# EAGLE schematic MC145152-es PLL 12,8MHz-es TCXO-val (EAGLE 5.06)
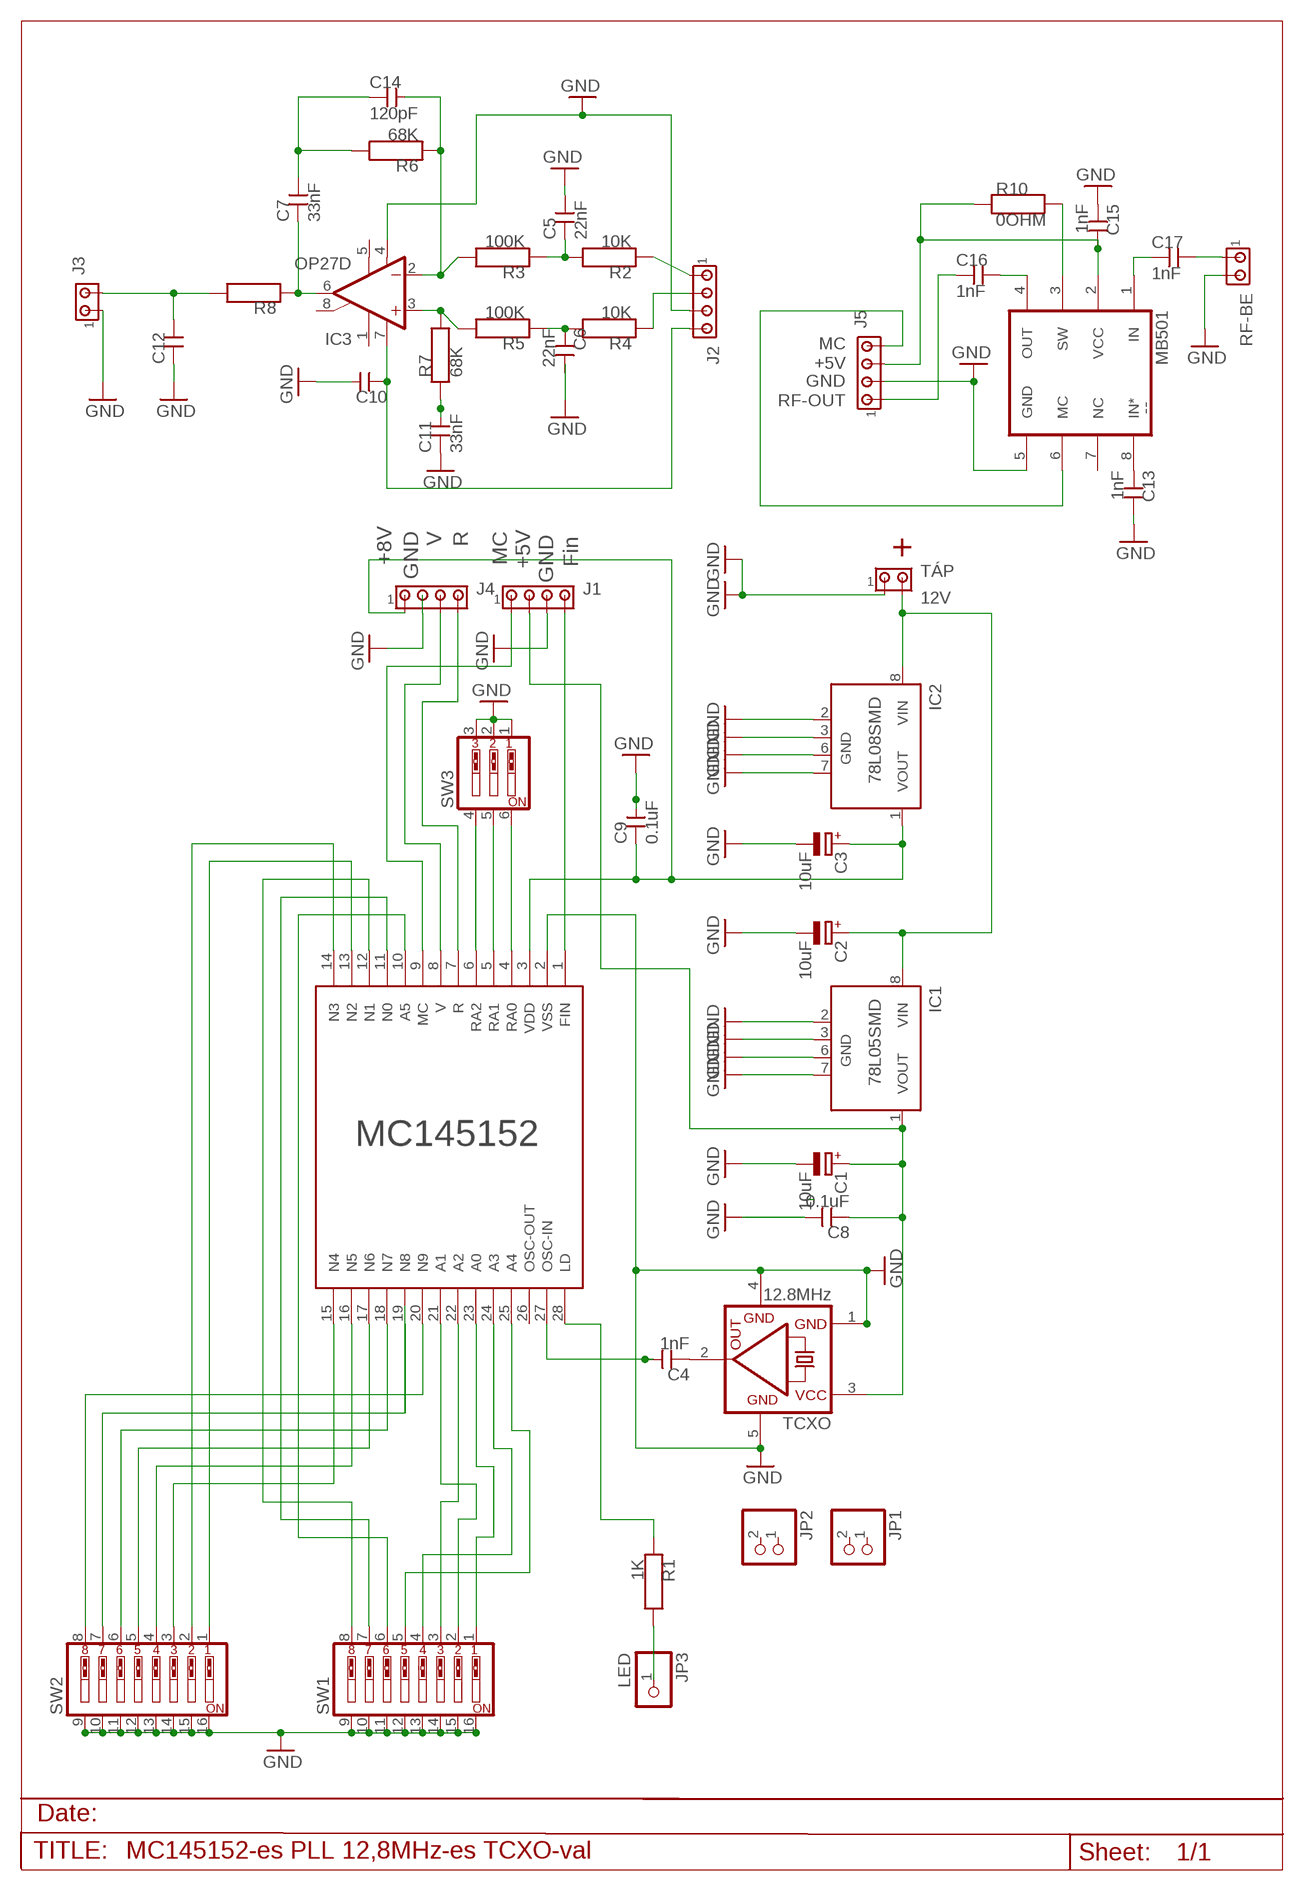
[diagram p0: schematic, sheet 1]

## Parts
C1  10uF  CPOL-EUE2,5-6E  [E2,5-6E]
C2  10uF  CPOL-EUE2,5-6E  [E2,5-6E]
C3  10uF  CPOL-EUE2,5-6E  [E2,5-6E]
C4  1nF  CAP-0805  [0805]
C5  22nF  CAP-0805  [0805]
C6  22nF  CAP-0805  [0805]
C7  33nF  CAP-0805  [0805]
C8  0.1uF  CAP-0805  [0805]
C9  0.1uF  CAP-0805  [0805]
C10  CAP-0805  [0805]
C11  33nF  CAP-0805  [0805]
C12  CAP-0805  [0805]
C13  1nF  CAP-0805  [0805]
C14  120pF  CAP-0805  [0805]
C15  1nF  CAP-0805  [0805]
C16  1nF  CAP-0805  [0805]
C17  1nF  CAP-0805  [0805]
IC1  78L05SMD  [SO08]
IC2  78L08SMD  [SO08]
IC3  OP27D  [SO08]
J1  MTA04-100  [10X04MTA]
J2  MTA04-100  [10X04MTA]
J3  MTA02-100  [10X02MTA]
J4  MTA04-100  [10X04MTA]
J5  MTA04-100  [10X04MTA]
JP1  PINHD-1X2_2.54  [1X02]
JP2  PINHD-1X2_2.54  [1X02]
JP3  LED  PINHD-1X1_2.54  [1X01]
MB501  MB501  [SO08]
MC145152  MC145152  [DIL28]
R1  1K  RES-0805  [0805]
R2  10K  RES-0805  [0805]
R3  100K  RES-0805  [0805]
R4  10K  RES-0805  [0805]
R5  100K  RES-0805  [0805]
R6  68K  RES-0805  [0805]
R7  68K  RES-0805  [0805]
R8  RES-0805  [0805]
R10  0OHM  RES-0805  [0805]
RF-BE  MTA02-100  [10X02MTA]
SW1  SW_DIP-8  [DIPSWITCH-08]
SW2  SW_DIP-8  [DIPSWITCH-08]
SW3  SW_DIP-3  [EDG-03]
TCXO  12.8MHz  TCXO  [TCXO]
TÁP  12V  MTA02-100  [10X02MTA]
U$1  FRAMES-A4  [FRAMES-A4]

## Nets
GND: C1.- C2.- C3.- C5.P$2 C6.P$2 C8.P$2 C9.P$2 C10.P$2 C11.P$1 C12.P$1 C13.P$2 C15.P$1 IC1.2(GND) IC1.3(GND) IC1.6(GND) IC1.7(GND) IC2.2(GND) IC2.3(GND) IC2.6(GND) IC2.7(GND) IC3.4(V-) J1.3 J2.3 J3.1 J4.2 J5.2 MB501.5(GND) MC145152.2(VSS) RF-BE.2 SW1.9 SW1.10 SW1.11 SW1.12 SW1.13 SW1.14 SW1.15 SW1.16 SW2.9 SW2.10 SW2.11 SW2.12 SW2.13 SW2.14 SW2.15 SW2.16 SW3.1 SW3.2 SW3.3 TCXO.1(GND) TCXO.4(GND1) TCXO.5(GND2) TÁP.1
N$1: C4.P$2 MC145152.27(OSC-IN)
N$2: MC145152.15(N4) SW2.3
N$3: J1.4 MC145152.1(FIN)
N$4: C3.+ C9.P$1 IC2.1(VOUT) J4.1 MC145152.3(VDD)
N$5: C2.+ IC1.8(VIN) IC2.8(VIN) TÁP.2
N$6: MC145152.23(A0) SW1.1
N$7: MC145152.21(A1) SW1.2
N$8: MC145152.22(A2) SW1.3
N$9: MC145152.24(A3) SW1.4
N$10: MC145152.25(A4) SW1.5
N$11: MC145152.10(A5) SW1.6
N$12: C1.+ C8.P$1 IC1.1(VOUT) J1.2 TCXO.3(VCC)
N$13: MC145152.12(N1) SW1.8
N$14: MC145152.13(N2) SW2.1
N$15: MC145152.14(N3) SW2.2
N$16: MC145152.17(N6) SW2.5
N$17: MC145152.18(N7) SW2.6
N$18: MC145152.19(N8) SW2.7
N$19: MC145152.20(N9) SW2.8
N$20: MC145152.11(N0) SW1.7
N$21: J4.4 MC145152.7(R)
N$23: MC145152.4(RA0) SW3.6
N$24: MC145152.5(RA1) SW3.5
N$25: MC145152.6(RA2) SW3.4
N$26: J4.3 MC145152.8(V)
N$28: J1.1 MC145152.9(MC)
N$29: MC145152.16(N5) SW2.4
N$31: MC145152.28(LD) R1.P$1
N$32: J2.1 R2.P$1
N$33: J2.2 R4.P$1
N$34: JP3.1 R1.P$2
N$36: C4.P$1 TCXO.2(OUT)
N$37: C5.P$1 R2.P$2 R3.P$1
N$38: C6.P$1 R4.P$2 R5.P$1
N$39: C14.P$2 IC3.2(-IN) R3.P$2 R6.P$1
N$40: IC3.3(+IN) R5.P$2 R7.P$2
N$41: J5.4 MB501.6(MC)
N$42: C10.P$1 IC3.7(V+) J2.4
N$43: C7.P$2 C14.P$1 R6.P$2
N$44: C7.P$1 IC3.6(OUT) R8.P$1
N$45: C12.P$2 J3.2 R8.P$2
N$47: C11.P$2 R7.P$1
N$48: C13.P$1 MB501.8(IN*)
N$49: C15.P$2 J5.3 MB501.2(VCC) R10.P$1
N$51: C16.P$1 J5.1
N$52: C16.P$2 MB501.4(OUT)
N$53: C17.P$1 MB501.1(IN)
N$54: C17.P$2 RF-BE.1
N$55: MB501.3(SW) R10.P$2
Unconnected: IC1.4(NC) IC1.5(NC) IC2.4(NC) IC2.5(NC) IC3.1(ON1) IC3.5(OPT) IC3.8(ON2) JP1.1 JP1.2 JP2.1 JP2.2 MB501.7(NC) MC145152.26(OSC-OUT)

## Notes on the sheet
- MC
- +5V
- GND
- RF-OUT
- +8V | GND | V | R | MC | +5V
- GND | Fin | +
- MC145152

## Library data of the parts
C1-C3 = rcl:CPOL-EU: POLARIZED CAPACITOR, European symbol
C4-C17 = scenix4:CAP-0805
IC1 IC2 = linear:78L*SMD: Positive VOLTAGE REGULATOR
IC3 = linear:OP27: OP AMP
J1 J2 J4 J5 = con-amp:MTA04-100: AMP connector
J3 RF-BE TÁP = con-amp:MTA02-100: AMP connector
JP1 JP2 = pinhead-1:PINHD-1X2: PIN HEADER
JP3 = pinhead-1:PINHD-1X1: PIN HEADER
MB501 = MB501:MB501: MB501-64/65,128/129 DIVIDER
MC145152 = MC145152:MC145152: PARALLEL PLL
R1-R8 R10 = scenix4:RES-0805
SW1 SW2 = SparkFun-7:SW_DIP-8: DIP Switch 8 Position Spark Fun Electronics SKU : COM-08034
SW3 = special:SW_DIP-3: DIP SWITCH
TCXO = TCXO:TCXO: TCXO
U$1 = FRAME-A4:FRAMES-A4: FRAMES-A4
